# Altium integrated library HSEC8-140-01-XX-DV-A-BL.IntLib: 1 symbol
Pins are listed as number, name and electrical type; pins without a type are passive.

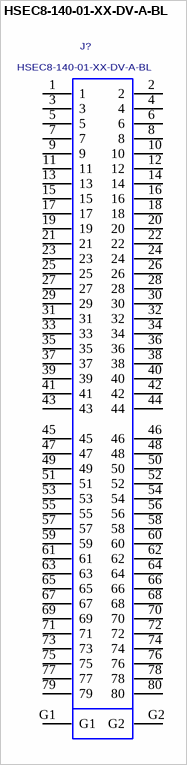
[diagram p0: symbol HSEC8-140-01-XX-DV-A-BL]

## HSEC8-140-01-XX-DV-A-BL
designator J?
0.8mm HIGH SPEED EDGE CARD ASSEMBLY.; MANUFACTURER: SAMTEC
footprint HSEC8-140-01-XX-DV-A-BL
pins: 1, 2, 3, 4, 5, 6, 7, 8, 9, 10, 11, 12, 13, 14, 15, 16, 17, 18, 19, 20, 21, 22, 23, 24, 25, 26, 27, 28, 29, 30, 31, 32, 33, 34, 35, 36, 37, 38, 39, 40, 41, 42, 43, 44, 45, 46, 47, 48, 49, 50, 51, 52, 53, 54, 55, 56, 57, 58, 59, 60, 61, 62, 63, 64, 65, 66, 67, 68, 69, 70, 71, 72, 73, 74, 75, 76, 77, 78, 79, 80, G1, G2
